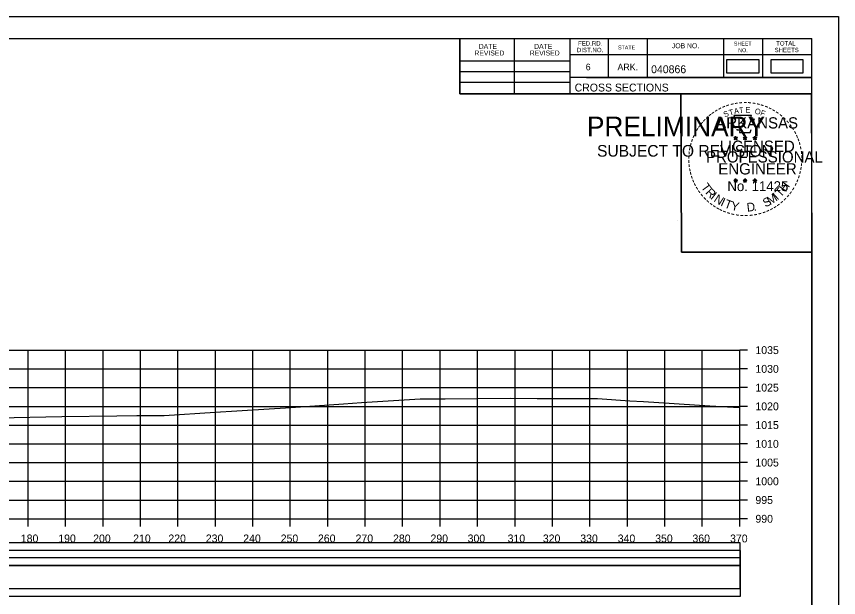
# Model space of a CAD drawing. Extents: x 1370565 to 1374448, y 301010 to 304637.
# Drawn here: x 1374228.4 to 1374447.9, y 301257.9 to 301413 of the extents above; entities that cross this region are included whole.
import ezdxf

# ---------------------------------------------------------------- set-up
doc = ezdxf.new("R2010")
doc.units = 0
for name, color, linetype in [('Default', 7, 'Continuous'), ('R_Axis', 7, 'Continuous'), ('R_Axis Annot', 7, 'Continuous'), ('R_Border', 7, 'Continuous'), ('R_Border PE', 7, 'Continuous'), ('R_Border Prem', 7, 'Continuous'), ('R_Drive', 7, 'Continuous'), ('R_Exist Surface', 7, 'Continuous'), ('R_Grid', 7, 'Continuous'), ('R_No Plot', 7, 'Continuous')]:
    doc.layers.add(name, color=color, linetype=linetype)

msp = doc.modelspace()

# ---------------------------------------------------------------- linework, layer by layer
at = {"layer": 'Default'}
for points in [[(1374418.01, 301397.93), (1374426.7, 301397.93), (1374426.7, 301401.37), (1374418.01, 301401.37)], [(1373981.44, 301268.58), (1374421.61, 301268.58), (1374421.61, 301272.57), (1373981.44, 301272.57)], [(1373981.44, 301260.35), (1374421.61, 301260.35), (1374421.61, 301268.5), (1373981.44, 301268.5)]]:
    msp.add_lwpolyline(points, close=True, dxfattribs=at)
at = {"layer": 'R_Axis'}
for p, q in [((1374421.52, 301278.95), (1374421.52, 301323.95)), ((1374423.62, 301323.95), (1374421.52, 301323.95)), ((1374423.62, 301318.95), (1374421.52, 301318.95)), ((1374423.62, 301313.95), (1374421.52, 301313.95)), ((1374423.62, 301308.95), (1374421.52, 301308.95)), ((1374423.62, 301303.95), (1374421.52, 301303.95)), ((1374423.62, 301298.95), (1374421.52, 301298.95)), ((1374423.62, 301293.95), (1374421.52, 301293.95)), ((1374423.62, 301288.95), (1374421.52, 301288.95)), ((1374423.62, 301283.95), (1374421.52, 301283.95)), ((1373981.52, 301278.95), (1374421.52, 301278.95)), ((1374231.52, 301276.85), (1374231.52, 301278.95)), ((1374241.52, 301276.85), (1374241.52, 301278.95)), ((1374251.52, 301276.85), (1374251.52, 301278.95)), ((1374261.52, 301276.85), (1374261.52, 301278.95)), ((1374271.52, 301276.85), (1374271.52, 301278.95)), ((1374281.52, 301276.85), (1374281.52, 301278.95)), ((1374291.52, 301276.85), (1374291.52, 301278.95)), ((1374301.52, 301276.85), (1374301.52, 301278.95)), ((1374311.52, 301276.85), (1374311.52, 301278.95)), ((1374321.52, 301276.85), (1374321.52, 301278.95)), ((1374331.52, 301276.85), (1374331.52, 301278.95)), ((1374341.52, 301276.85), (1374341.52, 301278.95)), ((1374351.52, 301276.85), (1374351.52, 301278.95)), ((1374361.52, 301276.85), (1374361.52, 301278.95)), ((1374371.52, 301276.85), (1374371.52, 301278.95)), ((1374381.52, 301276.85), (1374381.52, 301278.95)), ((1374391.52, 301276.85), (1374391.52, 301278.95)), ((1374401.52, 301276.85), (1374401.52, 301278.95)), ((1374411.52, 301276.85), (1374411.52, 301278.95)), ((1374421.52, 301276.85), (1374421.52, 301278.95)), ((1374423.62, 301278.95), (1374421.52, 301278.95))]:
    msp.add_line(p, q, dxfattribs=at)
at = {"layer": 'R_Border'}
for p, q in [((1373966.52, 301407.14), (1374440.79, 301407.14)), ((1374346.83, 301392.32), (1374346.83, 301407.14)), ((1374361.35, 301392.32), (1374361.35, 301407.14)), ((1374376.14, 301407.14), (1374376.14, 301392.32)), ((1374386.4, 301407.14), (1374386.4, 301396.73)), ((1374396.81, 301407.14), (1374396.81, 301396.73)), ((1374417.18, 301407.14), (1374417.18, 301396.73)), ((1374427.59, 301407.14), (1374427.59, 301396.73)), ((1374440.79, 301098.95), (1374440.79, 301407.14)), ((1374440.79, 301402.73), (1374376.14, 301402.73)), ((1374440.79, 301402.76), (1374440.79, 301402.76)), ((1374346.83, 301401.11), (1374376.14, 301401.11)), ((1374346.83, 301398.32), (1374376.14, 301398.32)), ((1374346.83, 301395.41), (1374376.14, 301395.41)), ((1374440.79, 301396.73), (1374376.14, 301396.73)), ((1374380.58, 301396.73), (1374440.79, 301396.73)), ((1374440.79, 301392.32), (1374346.83, 301392.32))]:
    msp.add_line(p, q, dxfattribs=at)
at = {"layer": 'R_Border PE'}
for p, q in [((1374419.92, 301380.7), (1374420.44, 301380.54)), ((1374419.92, 301380.7), (1374420.3, 301380.63)), ((1374419.92, 301380.7), (1374420.28, 301380.52)), ((1374420.12, 301380.09), (1374420.44, 301380.54)), ((1374420.12, 301380.09), (1374420.31, 301380.46)), ((1374420.12, 301380.09), (1374420.44, 301380.42)), ((1374420.44, 301381.08), (1374420.38, 301380.71)), ((1374420.44, 301380.54), (1374420.44, 301381.08)), ((1374420.44, 301381.08), (1374420.52, 301380.71)), ((1374420.97, 301380.7), (1374420.44, 301380.54)), ((1374420.76, 301380.09), (1374420.44, 301380.54)), ((1374420.76, 301380.09), (1374420.44, 301380.41)), ((1374420.97, 301380.7), (1374420.54, 301380.63)), ((1374420.76, 301380.09), (1374420.56, 301380.53)), ((1374420.97, 301380.7), (1374420.66, 301380.55)), ((1374422.43, 301380.7), (1374422.95, 301380.54)), ((1374422.43, 301380.7), (1374422.81, 301380.63)), ((1374422.43, 301380.7), (1374422.78, 301380.52)), ((1374422.63, 301380.09), (1374422.95, 301380.54)), ((1374422.63, 301380.09), (1374422.81, 301380.46)), ((1374422.63, 301380.09), (1374422.95, 301380.42)), ((1374422.95, 301381.08), (1374422.89, 301380.71)), ((1374422.95, 301380.54), (1374422.95, 301381.08)), ((1374422.95, 301381.08), (1374423.02, 301380.71)), ((1374423.47, 301380.7), (1374422.95, 301380.54)), ((1374423.27, 301380.09), (1374422.95, 301380.54)), ((1374423.27, 301380.09), (1374422.95, 301380.41)), ((1374423.47, 301380.7), (1374423.04, 301380.63)), ((1374423.27, 301380.09), (1374423.06, 301380.53)), ((1374423.47, 301380.7), (1374423.16, 301380.55)), ((1374425.07, 301380.68), (1374425.6, 301380.52)), ((1374425.07, 301380.68), (1374425.45, 301380.62)), ((1374425.07, 301380.68), (1374425.43, 301380.5)), ((1374425.27, 301380.07), (1374425.6, 301380.52)), ((1374425.27, 301380.07), (1374425.46, 301380.44)), ((1374425.27, 301380.07), (1374425.59, 301380.4)), ((1374425.6, 301381.07), (1374425.53, 301380.69)), ((1374425.92, 301380.07), (1374425.59, 301380.39)), ((1374425.6, 301380.52), (1374425.6, 301381.07)), ((1374425.6, 301381.07), (1374425.67, 301380.69)), ((1374426.12, 301380.68), (1374425.6, 301380.52)), ((1374425.92, 301380.07), (1374425.6, 301380.52)), ((1374426.12, 301380.68), (1374425.69, 301380.61)), ((1374425.92, 301380.07), (1374425.71, 301380.51)), ((1374426.12, 301380.68), (1374425.81, 301380.53)), ((1374419.92, 301369.34), (1374420.44, 301369.18)), ((1374419.92, 301369.34), (1374420.29, 301369.28)), ((1374419.92, 301369.34), (1374420.27, 301369.16)), ((1374420.11, 301368.73), (1374420.44, 301369.18)), ((1374420.11, 301368.73), (1374420.3, 301369.1)), ((1374420.11, 301368.73), (1374420.44, 301369.06)), ((1374420.44, 301369.72), (1374420.38, 301369.35)), ((1374420.44, 301369.18), (1374420.44, 301369.72)), ((1374420.44, 301369.72), (1374420.51, 301369.35)), ((1374420.96, 301369.34), (1374420.44, 301369.18)), ((1374420.76, 301368.73), (1374420.44, 301369.18)), ((1374420.76, 301368.73), (1374420.44, 301369.05)), ((1374420.96, 301369.34), (1374420.53, 301369.27)), ((1374420.76, 301368.73), (1374420.55, 301369.17)), ((1374420.96, 301369.34), (1374420.65, 301369.19)), ((1374422.42, 301369.34), (1374422.94, 301369.18)), ((1374422.42, 301369.34), (1374422.8, 301369.28)), ((1374422.42, 301369.34), (1374422.77, 301369.16)), ((1374422.62, 301368.73), (1374422.94, 301369.18)), ((1374422.62, 301368.73), (1374422.81, 301369.1)), ((1374422.62, 301368.73), (1374422.94, 301369.06)), ((1374422.94, 301369.72), (1374422.88, 301369.35)), ((1374422.94, 301369.18), (1374422.94, 301369.72)), ((1374422.94, 301369.72), (1374423.02, 301369.35)), ((1374423.46, 301369.34), (1374422.94, 301369.18)), ((1374423.26, 301368.73), (1374422.94, 301369.18)), ((1374423.26, 301368.73), (1374422.94, 301369.05)), ((1374423.46, 301369.34), (1374423.03, 301369.27)), ((1374423.26, 301368.73), (1374423.06, 301369.17)), ((1374423.46, 301369.34), (1374423.16, 301369.19)), ((1374425.07, 301369.33), (1374425.59, 301369.16)), ((1374425.07, 301369.33), (1374425.45, 301369.26)), ((1374425.07, 301369.33), (1374425.42, 301369.14)), ((1374425.27, 301368.72), (1374425.59, 301369.16)), ((1374425.27, 301368.72), (1374425.46, 301369.08)), ((1374425.27, 301368.72), (1374425.59, 301369.04)), ((1374425.59, 301369.71), (1374425.53, 301369.33)), ((1374425.59, 301369.16), (1374425.59, 301369.71)), ((1374425.59, 301369.71), (1374425.67, 301369.33)), ((1374426.11, 301369.33), (1374425.59, 301369.16)), ((1374425.91, 301368.72), (1374425.59, 301369.16)), ((1374425.91, 301368.72), (1374425.59, 301369.04)), ((1374426.11, 301369.33), (1374425.68, 301369.25)), ((1374425.91, 301368.72), (1374425.71, 301369.15)), ((1374426.11, 301369.33), (1374425.81, 301369.17))]:
    msp.add_line(p, q, dxfattribs=at)
for points in [[(1374419.98, 301386.52), (1374420.39, 301385.28)], [(1374425.25, 301385.14), (1374425.46, 301385.56), (1374424.43, 301385.53), (1374424.66, 301386.52), (1374419.98, 301386.52)], [(1374420.72, 301382.88), (1374420.72, 301382.75), (1374421.57, 301382.73), (1374421.48, 301382.02), (1374424.29, 301382.02), (1374424.59, 301382.82)], [(1374420.44, 301381.08), (1374420.76, 301380.09), (1374419.92, 301380.7), (1374420.97, 301380.7), (1374420.12, 301380.09), (1374420.44, 301381.08)], [(1374422.95, 301381.08), (1374423.27, 301380.09), (1374422.43, 301380.7), (1374423.47, 301380.7), (1374422.63, 301380.09), (1374422.95, 301381.08)], [(1374425.6, 301381.07), (1374425.92, 301380.07), (1374425.07, 301380.68), (1374426.12, 301380.68), (1374425.27, 301380.07), (1374425.6, 301381.07)], [(1374420.44, 301369.72), (1374420.76, 301368.73), (1374419.92, 301369.34), (1374420.96, 301369.34), (1374420.11, 301368.73), (1374420.44, 301369.72)], [(1374422.94, 301369.72), (1374423.26, 301368.73), (1374422.42, 301369.34), (1374423.46, 301369.34), (1374422.62, 301368.73), (1374422.94, 301369.72)], [(1374425.59, 301369.71), (1374425.91, 301368.72), (1374425.07, 301369.33), (1374426.11, 301369.33), (1374425.27, 301368.72), (1374425.59, 301369.71)]]:
    msp.add_lwpolyline(points, dxfattribs=at)
for centre, radius in [((1374420.44, 301380.53), 0.258), ((1374420.44, 301380.53), 0.217), ((1374420.44, 301380.53), 0.174), ((1374420.44, 301380.53), 0.149), ((1374420.44, 301380.53), 0.112), ((1374420.44, 301380.53), 0.0743), ((1374420.44, 301380.53), 0.0445), ((1374422.95, 301380.53), 0.258), ((1374422.95, 301380.53), 0.217), ((1374422.95, 301380.53), 0.174), ((1374422.95, 301380.53), 0.149), ((1374422.95, 301380.53), 0.112), ((1374422.95, 301380.53), 0.0743), ((1374422.95, 301380.53), 0.0445), ((1374425.59, 301380.52), 0.258), ((1374425.59, 301380.52), 0.217), ((1374425.59, 301380.52), 0.174), ((1374425.59, 301380.52), 0.149), ((1374425.59, 301380.52), 0.112), ((1374425.59, 301380.52), 0.0743), ((1374425.59, 301380.52), 0.0445), ((1374420.44, 301369.18), 0.258), ((1374420.44, 301369.18), 0.217), ((1374420.44, 301369.18), 0.174), ((1374420.44, 301369.18), 0.149), ((1374420.44, 301369.18), 0.112), ((1374420.44, 301369.18), 0.0743), ((1374420.44, 301369.18), 0.0445), ((1374422.94, 301369.18), 0.258), ((1374422.94, 301369.18), 0.217), ((1374422.94, 301369.18), 0.174), ((1374422.94, 301369.18), 0.149), ((1374422.94, 301369.18), 0.112), ((1374422.94, 301369.18), 0.0743), ((1374422.94, 301369.18), 0.0445), ((1374425.59, 301369.16), 0.258), ((1374425.59, 301369.16), 0.217), ((1374425.59, 301369.16), 0.174), ((1374425.59, 301369.16), 0.149), ((1374425.59, 301369.16), 0.112), ((1374425.59, 301369.16), 0.0743), ((1374425.59, 301369.16), 0.0445)]:
    msp.add_circle(centre, radius, dxfattribs=at)
at = {"layer": 'R_Drive'}
for points in [[(1374429.82, 301397.94), (1374438.51, 301397.94), (1374438.51, 301401.38), (1374429.82, 301401.38)], [(1373981.52, 301266.49), (1374421.73, 301266.49), (1374421.73, 301270.48), (1373981.52, 301270.48)], [(1373981.52, 301258.34), (1374421.73, 301258.34), (1374421.73, 301266.49), (1373981.52, 301266.49)]]:
    msp.add_lwpolyline(points, close=True, dxfattribs=at)
at = {"layer": 'R_Exist Surface'}
msp.add_lwpolyline([(1374223.45, 301305.88), (1374240.5, 301306.28), (1374255.23, 301306.4), (1374260.55, 301306.49), (1374267.8, 301306.5), (1374281.42, 301307.37), (1374287.28, 301307.75), (1374301.63, 301308.68), (1374315.72, 301309.6), (1374320.49, 301309.94), (1374336.22, 301310.93), (1374339.55, 301310.96), (1374342.91, 301310.99), (1374360.38, 301311.12), (1374367.48, 301311.08), (1374383.58, 301311.01), (1374392.19, 301310.44), (1374395.84, 301310.23), (1374413.54, 301309.12), (1374421.49, 301308.62), (1374421.52, 301308.62)], dxfattribs=at)
at = {"layer": 'R_Grid'}
for p, q in [((1373981.52, 301323.95), (1374421.52, 301323.95)), ((1374231.52, 301278.95), (1374231.52, 301323.95)), ((1374241.52, 301278.95), (1374241.52, 301323.95)), ((1374251.52, 301278.95), (1374251.52, 301323.95)), ((1374261.52, 301278.95), (1374261.52, 301323.95)), ((1374271.52, 301278.95), (1374271.52, 301323.95)), ((1374281.52, 301278.95), (1374281.52, 301323.95)), ((1374291.52, 301278.95), (1374291.52, 301323.95)), ((1374301.52, 301278.95), (1374301.52, 301323.95)), ((1374311.52, 301278.95), (1374311.52, 301323.95)), ((1374321.52, 301278.95), (1374321.52, 301323.95)), ((1374331.52, 301278.95), (1374331.52, 301323.95)), ((1374341.52, 301278.95), (1374341.52, 301323.95)), ((1374351.52, 301278.95), (1374351.52, 301323.95)), ((1374361.52, 301278.95), (1374361.52, 301323.95)), ((1374371.52, 301278.95), (1374371.52, 301323.95)), ((1374381.52, 301278.95), (1374381.52, 301323.95)), ((1374391.52, 301278.95), (1374391.52, 301323.95)), ((1374401.52, 301278.95), (1374401.52, 301323.95)), ((1374411.52, 301278.95), (1374411.52, 301323.95)), ((1374421.52, 301278.95), (1374421.52, 301323.95)), ((1373981.52, 301318.95), (1374421.52, 301318.95)), ((1373981.52, 301313.95), (1374421.52, 301313.95)), ((1373981.52, 301308.95), (1374421.52, 301308.95)), ((1373981.52, 301303.95), (1374421.52, 301303.95)), ((1373981.52, 301298.95), (1374421.52, 301298.95)), ((1373981.52, 301293.95), (1374421.52, 301293.95)), ((1373981.52, 301288.95), (1374421.52, 301288.95)), ((1373981.52, 301283.95), (1374421.52, 301283.95)), ((1373981.52, 301278.95), (1374421.52, 301278.95))]:
    msp.add_line(p, q, dxfattribs=at)
at = {"layer": 'R_No Plot'}
for p, q in [((1373947.92, 301412.98), (1374447.92, 301412.98)), ((1374404.85, 301358.64), (1374404.85, 301358.64))]:
    msp.add_line(p, q, dxfattribs=at)
for points in [[(1373947.91, 301412.98), (1374447.92, 301412.98), (1374447.92, 301092.98), (1373947.91, 301092.98)], [(1374317.4, 301407.14), (1374346.83, 301407.14), (1374346.83, 301392.32), (1374371, 301392.32), (1374405.8, 301392.32), (1374405.98, 301350.08), (1374440.79, 301350.08), (1374440.79, 301098.95), (1373966.52, 301098.95), (1373966.52, 301407.14)], [(1374405.8, 301392.32), (1374440.61, 301392.32), (1374440.79, 301350.08), (1374405.98, 301350.08)]]:
    msp.add_lwpolyline(points, close=True, dxfattribs=at)

# ---------------------------------------------------------------- texts
at = {"layer": 'R_Axis Annot'}
for s, p in [('1035', (1374425.72, 301322.9)), ('1030', (1374425.72, 301317.9)), ('1025', (1374425.72, 301312.9)), ('1020', (1374425.72, 301307.9)), ('1015', (1374425.72, 301302.9)), ('1010', (1374425.72, 301297.9)), ('1005', (1374425.72, 301292.9)), ('1000', (1374425.72, 301287.9)), ('995', (1374425.72, 301282.9)), ('990', (1374425.72, 301277.9)), ('180', (1374229.55, 301272.65)), ('190', (1374239.55, 301272.65)), ('200', (1374248.87, 301272.65)), ('210', (1374259.55, 301272.65)), ('220', (1374268.95, 301272.65)), ('230', (1374278.95, 301272.65)), ('240', (1374288.95, 301272.65)), ('250', (1374298.95, 301272.65)), ('260', (1374308.9, 301272.65)), ('270', (1374318.95, 301272.65)), ('280', (1374328.95, 301272.65)), ('290', (1374338.95, 301272.65)), ('300', (1374348.87, 301272.65)), ('310', (1374359.55, 301272.65)), ('320', (1374368.95, 301272.65)), ('330', (1374378.95, 301272.65)), ('340', (1374388.95, 301272.65)), ('350', (1374398.95, 301272.65)), ('360', (1374408.9, 301272.65)), ('370', (1374418.95, 301272.65))]:
    msp.add_text(s, height=2.1, dxfattribs=at).set_placement(p)
at = {"layer": 'R_Border'}
for s, height, p in [('FED.RD.', 1.173, (1374378.36, 301405.22)), ('SHEET', 1.026, (1374419.97, 301405.22)), ('TOTAL', 1.173, (1374431.25, 301405.22)), ('REVISED', 1.319, (1374350.67, 301402.57)), ('DATE', 1.319, (1374351.84, 301404.34)), ('REVISED', 1.319, (1374365.46, 301402.57)), ('DATE', 1.319, (1374366.63, 301404.34)), ('DIST.NO.', 1.173, (1374378.06, 301403.45)), ('STATE', 1.026, (1374389.04, 301404.2)), ('JOB NO.', 1.319, (1374403.41, 301404.5)), ('NO.', 1.026, (1374421.14, 301403.45)), ('SHEETS', 1.173, (1374430.83, 301403.45)), ('6', 1.76, (1374380.4, 301398.62)), ('ARK.', 1.758, (1374388.89, 301398.62)), ('040866', 2.1, (1374397.86, 301397.84)), ('CROSS SECTIONS', 2.1, (1374377.44, 301392.96))]:
    msp.add_text(s, height=height, rotation=360, dxfattribs=at).set_placement(p)
at = {"layer": 'R_Border PE'}
for s, height, rotation, p in [('-', 2.4, 28.7918, (1374416.2, 301387.33)), ('-', 2.4, 24.3072, (1374417.15, 301387.81)), ('-', 2.4, 19.1761, (1374418.1, 301388.21)), ('-', 2.4, 13.6301, (1374419.23, 301388.57)), ('A', 1.5, 11.2132, (1374420.13, 301386.91)), ('-', 2.4, 10.2193, (1374420.25, 301388.81)), ('T', 1.5, 6.0228, (1374421.4, 301387.16)), ('-', 2.4, 5.8968, (1374421.34, 301388.98)), ('-', 2.4, 0.1862, (1374422.5, 301389.09)), ('E', 1.5, 0.8323, (1374423.06, 301387.32)), ('-', 2.4, 357.743, (1374423.58, 301389.07)), ('-', 2.4, 352.1617, (1374424.7, 301388.98)), ('O', 1.5, 350.4515, (1374425.46, 301387.01)), ('-', 2.4, 347.2049, (1374425.78, 301388.81)), ('-', 2.4, 342.3362, (1374426.73, 301388.58)), ('-', 2.4, 337.8551, (1374427.83, 301388.25)), ('-', 2.4, 334.1211, (1374428.78, 301387.84)), ('-', 2.4, 42.9622, (1374413.08, 301384.99)), ('-', 2.4, 38.9507, (1374413.73, 301385.62)), ('-', 2.4, 36.2317, (1374414.44, 301386.18)), ('-', 2.4, 34.0636, (1374415.31, 301386.78)), ('S', 1.5, 21.594, (1374417.52, 301386.04)), ('T', 1.5, 16.4036, (1374418.89, 301386.53)), ('F', 1.5, 340.0707, (1374426.89, 301386.67)), ('-', 2.4, 329.6409, (1374429.65, 301387.41)), ('-', 2.4, 325.8627, (1374430.61, 301386.87)), ('-', 2.4, 320.5297, (1374431.53, 301386.23)), ('-', 2.4, 54.2325, (1374411.18, 301382.69)), ('-', 2.4, 50.6142, (1374411.8, 301383.54)), ('-', 2.4, 48.4231, (1374412.41, 301384.27)), ('ARKANSAS', 3, 360, (1374415.26, 301383.09)), ('-', 2.4, 315.5786, (1374432.43, 301385.5)), ('-', 2.4, 309.8797, (1374433.28, 301384.68)), ('-', 2.4, 306.6522, (1374434.07, 301383.77)), ('-', 2.4, 62.8713, (1374410.23, 301380.98)), ('-', 2.4, 58.0706, (1374410.69, 301381.9)), ('-', 2.1, 303.6753, (1374434.8, 301382.92)), ('-', 2.4, 299.6684, (1374435.27, 301382.01)), ('-', 2.4, 72.3945, (1374409.51, 301379.12)), ('-', 2.4, 67.7743, (1374409.84, 301380.07)), ('LICENSED', 3, 360, (1374416.16, 301376.86)), ('DWB', 0.015, 360, (1374420.43, 301380.53)), ('DWB', 0.015, 360, (1374422.93, 301380.53)), ('DWB', 0.015, 360, (1374425.58, 301380.51)), ('-', 2.4, 294.6628, (1374435.76, 301381.09)), ('-', 2.4, 290.5728, (1374436.15, 301380.23)), ('-', 2.4, 81.2013, (1374409.01, 301376.98)), ('-', 2.4, 75.461, (1374409.21, 301378.05)), ('-', 2.4, 285.1233, (1374436.5, 301379.36)), ('-', 2.4, 280.5493, (1374436.8, 301378.25)), ('-', 2.4, 89.0622, (1374408.86, 301374.89)), ('-', 2.4, 85.1863, (1374408.9, 301375.94)), ('PROFESSIONAL', 3, 360, (1374412.52, 301374.01)), ('-', 2.4, 276.5962, (1374437.04, 301377.09)), ('-', 2.4, 274.3301, (1374437.13, 301376.01)), ('-', 2.4, 94.1959, (1374408.92, 301373.81)), ('-', 2.4, 98.9479, (1374409.02, 301372.8)), ('ENGINEER', 3, 360, (1374415.8, 301370.82)), ('-', 2.4, 263.5172, (1374437.15, 301374.06)), ('-', 2.4, 269.9407, (1374437.18, 301375.06)), ('-', 2.4, 101.7149, (1374409.23, 301371.71)), ('-', 2.4, 105.4578, (1374409.47, 301370.81)), ('-', 2.4, 255.7626, (1374436.88, 301372.07)), ('-', 2.4, 260.9953, (1374437.05, 301373.08)), ('-', 2.4, 109.0874, (1374409.79, 301369.87)), ('-', 2.4, 114.0643, (1374410.17, 301368.97)), ('T', 2.31, 306.0406, (1374411.08, 301367.43)), ('No. 11425', 2.635, 360, (1374418.24, 301366.39)), ('DWB', 0.015, 360, (1374420.42, 301369.17)), ('DWB', 0.015, 360, (1374422.92, 301369.17)), ('DWB', 0.015, 360, (1374425.57, 301369.15)), ('H', 2.31, 54.6088, (1374433.76, 301365.99)), ('-', 2.4, 247.8887, (1374436.27, 301369.98)), ('-', 2.4, 252.8681, (1374436.61, 301370.99)), ('-', 2.4, 115.7289, (1374410.63, 301368.05)), ('-', 2.4, 120.4471, (1374411.17, 301367.17)), ('-', 2.4, 125.8934, (1374411.77, 301366.32)), ('R', 2.31, 314.005, (1374412.22, 301365.86)), ('T', 2.31, 46.6444, (1374432.42, 301364.57)), ('-', 2.4, 239.0712, (1374435.29, 301367.9)), ('-', 2.4, 244.6197, (1374435.88, 301369.03)), ('-', 2.4, 130.7181, (1374412.46, 301365.5)), ('-', 2.4, 134.2238, (1374413.24, 301364.68)), ('I', 2.31, 321.9694, (1374413.57, 301364.46)), ('N', 2.31, 326.5002, (1374414.42, 301363.76)), ('I', 2.31, 335.3603, (1374416.24, 301362.58)), ('S', 2.31, 26.9312, (1374428.4, 301361.98)), ('M', 2.31, 32.6563, (1374429.66, 301362.59)), ('I', 2.31, 42.1136, (1374431.58, 301363.86)), ('-', 2.4, 225.7653, (1374433.32, 301365.23)), ('-', 2.4, 231.2538, (1374434.04, 301366.08)), ('-', 2.4, 233.8452, (1374434.69, 301366.92)), ('-', 2.4, 138.9338, (1374414.03, 301363.98)), ('-', 2.4, 144.6463, (1374414.86, 301363.37)), ('-', 2.4, 148.0898, (1374415.7, 301362.82)), ('-', 2.4, 151.5704, (1374416.57, 301362.33)), ('T', 2.31, 339.8912, (1374417.23, 301362.09)), ('Y', 2.31, 347.8556, (1374419.05, 301361.42)), ('D', 2.31, 6.3969, (1374423.53, 301360.88)), ('-', 2.4, 212.2491, (1374430.92, 301363.18)), ('-', 2.4, 215.7363, (1374431.72, 301363.76)), ('-', 2.4, 221.0851, (1374432.54, 301364.47)), ('-', 2.4, 154.6002, (1374417.35, 301361.96)), ('-', 2.4, 158.5612, (1374418.29, 301361.58)), ('-', 2.4, 162.7983, (1374419.32, 301361.26)), ('-', 2.4, 167.5555, (1374420.39, 301361.01)), ('-', 2.4, 173.1155, (1374421.55, 301360.85)), ('-', 2.4, 176.5183, (1374422.67, 301360.77)), ('-', 2.4, 181.5918, (1374423.79, 301360.8)), ('-', 2.4, 185.8167, (1374425, 301360.91)), ('-', 2.4, 191.2858, (1374426.11, 301361.11)), ('.', 2.31, 13.7642, (1374425.32, 301361.07)), ('-', 2.4, 195.4743, (1374427.2, 301361.41)), ('-', 2.4, 200.7184, (1374428.21, 301361.77)), ('-', 2.4, 204.2516, (1374429.14, 301362.18)), ('-', 2.4, 207.3568, (1374430.08, 301362.66))]:
    msp.add_text(s, height=height, rotation=rotation, dxfattribs=at).set_placement(p)
at = {"layer": 'R_Border Prem'}
for s, height, p in [('PRELIMINARY', 5.25, (1374380.72, 301381.01)), ('DWB', 0.015, (1374381.84, 301383.79)), ('SUBJECT TO REVISION', 3.1127, (1374383.43, 301375.57))]:
    msp.add_text(s, height=height, rotation=360, dxfattribs=at).set_placement(p)

doc.saveas('drawing.dxf')
